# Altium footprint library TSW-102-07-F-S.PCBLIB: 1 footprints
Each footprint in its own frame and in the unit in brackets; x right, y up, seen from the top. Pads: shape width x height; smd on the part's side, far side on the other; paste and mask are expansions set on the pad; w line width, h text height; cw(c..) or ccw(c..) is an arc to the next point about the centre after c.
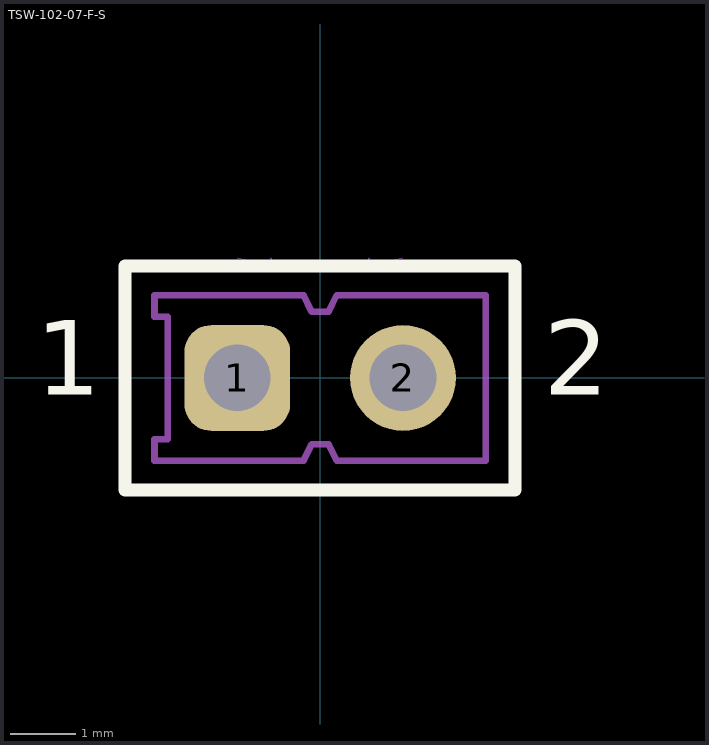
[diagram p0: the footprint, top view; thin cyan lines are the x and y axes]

## TSW-102-07-F-S [mm]
pads (2):
  rrect50% 1.62x1.62 hole 1.02: 1(-1.27,0)
  round 1.62 hole 1.02: 2(1.27,0)
Top Overlay:
  lines w0.2: -2.99,-1.72 2.985,-1.72 2.985,1.72 -2.99,1.72 -2.99,-1.72
  text "2" at 3.429,-0.635 h1.97
  text "1" at -4.36,-0.635 h1.97
Top Solder:
  circle w0: c-1.27,0 r0.861
  circle w0: c1.27,0 r0.861
Bottom Solder:
  circle w0: c-1.27,0 r0.861
  circle w0: c1.27,0 r0.861
Mechanical 16:
  lines w0.1: -2.54,-1.27 -0.254,-1.27 -0.13,-1.016 0,-1.016 0.13,-1.016 0.254,-1.27 2.54,-1.27 2.54,1.27 0.254,1.27 0.13,1.016 0,1.016 -0.13,1.016 -0.254,1.27 -2.54,1.27 -2.54,0.94 -2.337,0.94 -2.337,-0.94 -2.54,-0.94 -2.54,-1.27 ; -1.588,-0.318 -0.952,-0.318 -0.952,0.318 -1.588,0.318 -1.588,-0.318 ; 0.952,-0.318 1.588,-0.318 1.588,0.318 0.952,0.318 0.952,-0.318
  text "1" at -4.36,-0.635 h1.97
  text "2" at 3.429,-0.635 h1.97
Mechanical 40:
  lines w0: -1.27,1.842 -0.635,1.683 -0.762,1.842 ; 0.698,1.762 0.635,1.683 ; 0.762,1.842 0.635,1.683 ; 1.27,1.842 0.635,1.683
Mechanical 42:
  lines w0.1: -2.99,-1.72 3.007,-1.72 3.007,1.72 -2.99,1.72 -2.99,-1.72
3D body "TSW-102-07-F-S.stp": height 8.38, standoff -2.54, extent -2.582,-1.28 2.625,1.26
